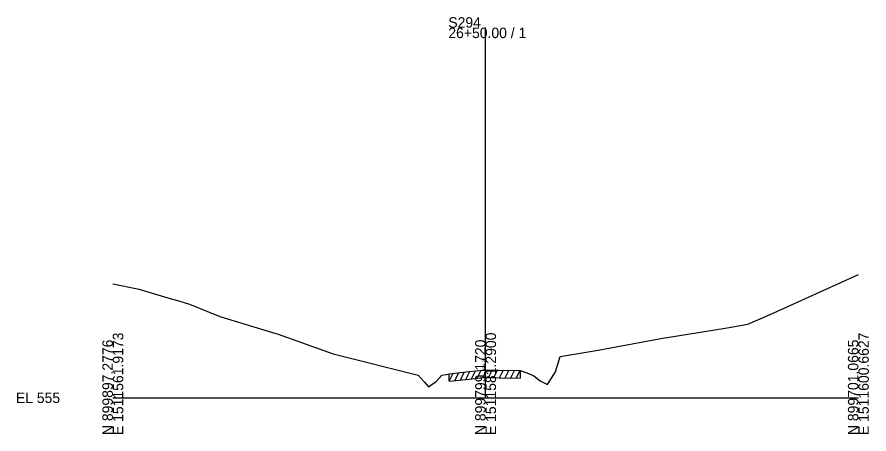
# Model space of a CAD drawing. Extents: x 974 to 2203, y -10 to 19041.
# Drawn here: x 1974.3 to 2202.8, y 12990.3 to 13102.1 of the extents above; entities that cross this region are included whole.
import ezdxf

# ---------------------------------------------------------------- set-up
doc = ezdxf.new("R2010")
doc.units = 0
for name, color, linetype in [('RD_GPK_XS_Cell', 7, 'Continuous'), ('RD_XS_ExGround', 7, 'Continuous'), ('RD_XS_ExPaveRet', 7, 'Continuous'), ('RD_XS_TX_Elev_EX', 7, 'Continuous')]:
    doc.layers.add(name, color=color, linetype=linetype)

msp = doc.modelspace()

# ---------------------------------------------------------------- linework, layer by layer
at = {"layer": 'RD_GPK_XS_Cell'}
for p, q in [((2100, 13000), (2100, 13099.23)), ((2000, 13000), (2100, 13000)), ((2100, 13000), (2200, 13000))]:
    msp.add_line(p, q, dxfattribs=at)
at = {"layer": 'RD_XS_ExGround'}
msp.add_lwpolyline([(2000, 13030.53), (2007.05, 13029.09), (2008.47, 13028.68), (2014.77, 13026.84), (2017.99, 13025.94), (2020.57, 13025.08), (2028.7, 13021.77), (2042.84, 13017.49), (2044.37, 13017.1), (2059.07, 13011.77), (2081.94, 13006.07), (2083.55, 13004.26), (2084.66, 13002.95), (2086.74, 13004.4), (2088.29, 13006.03), (2089.44, 13006.28), (2090.24, 13006.46), (2095.59, 13007.01), (2099.37, 13007.45), (2100, 13007.44), (2103.62, 13007.38), (2109.29, 13007.28), (2111.06, 13006.65), (2112.92, 13005.91), (2114.66, 13004.55), (2116.6, 13003.54), (2118.77, 13006.95), (2119.99, 13011.06), (2130.17, 13012.8), (2146.97, 13015.91), (2164.27, 13018.65), (2164.81, 13018.78), (2170.37, 13019.71), (2176.35, 13022.32), (2200, 13033.08)], dxfattribs=at)
at = {"layer": 'RD_XS_ExPaveRet'}
for p, q in [((2090.24, 13004.46), (2091.29, 13006.57)), ((2090.24, 13004.46), (2090.24, 13006.46)), ((2091.74, 13004.61), (2092.79, 13006.72)), ((2093.24, 13004.77), (2094.29, 13006.87)), ((2094.74, 13004.92), (2095.8, 13007.03)), ((2096.24, 13005.08), (2097.3, 13007.21)), ((2097.74, 13005.26), (2098.8, 13007.39)), ((2099.24, 13005.44), (2100.24, 13007.44)), ((2100.74, 13005.43), (2101.73, 13007.41)), ((2102.24, 13005.4), (2103.23, 13007.38)), ((2103.74, 13005.37), (2104.73, 13007.36)), ((2105.24, 13005.35), (2106.23, 13007.33)), ((2106.74, 13005.32), (2107.73, 13007.31)), ((2108.24, 13005.3), (2109.23, 13007.28)), ((2109.29, 13007.28), (2109.29, 13005.28)), ((2090.24, 13004.46), (2095.59, 13005.01)), ((2095.59, 13005.01), (2099.37, 13005.45)), ((2099.37, 13005.45), (2100, 13005.44)), ((2100, 13005.44), (2103.62, 13005.38)), ((2103.62, 13005.38), (2109.29, 13005.28))]:
    msp.add_line(p, q, dxfattribs=at)

# ---------------------------------------------------------------- texts
at = {"layer": 'RD_GPK_XS_Cell'}
for s, p in [('S294', (2090, 13099.23)), ('26+50.00 / 1', (2090, 13096.43)), ('EL 555', (1974, 12998.6))]:
    msp.add_text(s, height=2.8, dxfattribs=at).set_placement(p)
for s, p in [('E 1511561.9173', (2002.8, 12990)), ('E 1511581.2900', (2102.8, 12990)), ('E 1511600.6627', (2202.8, 12990)), ('N 899897.2776', (2000, 12990)), ('N 899799.1720', (2100, 12990)), ('N 899701.0665', (2200, 12990))]:
    msp.add_text(s, height=2.8, rotation=90, dxfattribs=at).set_placement(p)
at = {"layer": 'RD_XS_TX_Elev_EX'}
msp.add_text('558.72', height=0.75, rotation=90, dxfattribs=at).set_placement((2100, 13007.44))

doc.saveas('drawing.dxf')
